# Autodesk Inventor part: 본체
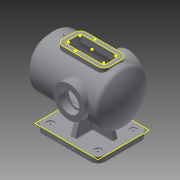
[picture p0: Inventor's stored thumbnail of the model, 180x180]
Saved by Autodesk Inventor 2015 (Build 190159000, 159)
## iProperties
Created: 2021-11
Part Number: 본체
Material: 일반
Document SubType Name: Modeling
Designer: 1016549
Density: 1 g/cm^3
Appearance: 기본값
Author: 1016549
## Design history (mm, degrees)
sketch "스케치1"
  geometry: C1 r 65 at (0, 0); 1 further point
  constraints: 1 centre point, 1 coincident
  dimensions: "d0" = 130 diameter of C1
extrude "돌출1" new body sketch "스케치1" stored distance "d1" = 200; taper "d2" = 0 deg
sketch "스케치2"
  geometry: L1 (100, 65)-(100, -65) reference; L2 (100, -65)-(-100, -65) reference; L3 (-100, -65)-(-100, 65) reference; L4 (-100, 65)-(100, 65) reference; L5 (100, 0)-(-100, 0); A1 r 100 centre (0, 0) between (-75.993, 65) and (-100, 0); 1 further point
  constraints: 3 midpoint, 2 end point, 2 point on circle, 1 centre point, 1 horizontal, 1 point on line
  dimensions: "d3" = 100 radius of A1
revolve "회전1" sketch "스케치2" stored, may be unused: angle "d4" = 90 deg
fillet "모깎기1" dims "d5" = 10
feature "쉘1" dims "d6" = 10
sketch "스케치3"
  geometry: C1 r 55 at (0, 0) reference; C2 r 65 at (0, 0) reference; C3 r 65 at (0, 0)
  constraints: 1 centre point, 1 coincident, 1 concentric
extrude "돌출2" join sketch "스케치3" distance "d7" = 15; taper "d8" = 0 deg
sketch "스케치4"
  geometry: C1 r 65 at (0, 0) reference; C2 r 47.5 at (0, 0)
  constraints: 1 centre point, 1 coincident
  dimensions: "d9" = 95 diameter of C2
extrude "돌출3" join sketch "스케치4" distance "d10" = 10; taper "d11" = 0 deg
sketch "스케치5"
  geometry: C1 r 47.5 at (0, 0) reference
hole "구멍1" sketch "스케치5" at (0, 0) diameter "d12" = 65; stored, may be unused: countersink angle "d16" = 90 deg, drill point angle "d18" = 118 deg; dims "d13" = 6, "d14" = 4, "d15" = 2, "d17" = 30
fillet "모깎기2" dims "d19" = 10
sketch "스케치6"
  geometry: 1 further point
node "작업 평면2"
sketch "스케치7"
  geometry: L1 (-80, -65)-(80, -65); L2 (80, -65)-(80, 65); L3 (80, 65)-(-80, 65); L4 (-80, 65)-(-80, -65); 3 further points
  constraints: 8 end point, 2 midpoint, 2 parallel, 1 horizontal, 1 horizontal alignment, 1 perpendicular, 1 vertical alignment
  dimensions: "d22" = 130 distance of L1.end L2.end; "d23" = 160 distance of L2.end L3.end
extrude "돌출4" join sketch "스케치7" distance "d24" = 14; taper "d25" = 0 deg
sketch "스케치8"
  geometry: L1 (60, -7)-(-60, -7); L2 (-60, -7)-(-60, 7); L3 (-60, 7)-(60, 7); L4 (60, 7)-(60, -7); L5 (60, -7)-(-60, 7); L6 (-60, -7)-(60, 7); L7 (7, -50)-(-7, -50); L8 (-7, -50)-(-7, 50); L9 (-7, 50)-(7, 50); L10 (7, 50)-(7, -50); L11 (7, -50)-(-7, 50); L12 (-7, -50)-(7, 50); 1 further point
  constraints: 24 end point, 4 midpoint, 4 parallel, 2 horizontal, 2 perpendicular
  dimensions: "d28" = 120 distance of L1.start L1.end; "d29" = 14 distance of L3.end L1.start; "d30" = 14 distance of L8.end L9.end; "d31" = 100 distance of L9.end L7.start
extrude "돌출5" join sketch "스케치8" stored distance "d26" = 14; taper "d27" = 0 deg
sketch "스케치9"
  geometry: L1 (60, -7)-(7, -7) reference; L2 (7, -7)-(7, -50) reference; L3 (7, -50)-(-7, -50) reference; L4 (-7, -50)-(-7, -7) reference; L5 (-7, -7)-(-60, -7) reference; L6 (-60, -7)-(-60, 7) reference; L7 (-60, 7)-(-7, 7) reference; L8 (-7, 7)-(-7, 50) reference; L9 (-7, 50)-(7, 50) reference; L10 (7, 50)-(7, 7) reference; L11 (7, 7)-(60, 7) reference; L12 (60, 7)-(60, -7) reference; L13 (-80, -65)-(80, -65) reference; L14 (80, -65)-(80, 65) reference; L15 (80, 65)-(-80, 65) reference; L16 (-80, 65)-(-80, -65) reference; 1 further point
feature "면 기울기1" dims angle "d32" = 20 deg
feature "면 기울기2" dims angle "d33" = 20 deg
feature "면 기울기3" dims angle "d34" = 20 deg
feature "면 기울기4" dims angle "d35" = 20 deg
node "작업 평면3"
sketch "스케치10"
  geometry: L1 (110, -47.5)-(110, 47.5) reference; C1 r 40 at (-17, 0); 2 further points
  constraints: 1 centre point, 1 coincident, 1 horizontal alignment, 1 midpoint
  dimensions: "d112" = 127 distance from line of point (-17, 0) L1
extrude "돌출6" join sketch "스케치10" stored distance "d38" = 14; taper "d39" = 0 deg
node "작업 평면4"
sketch "스케치11"
  geometry: L1 (-60, 30)-(60, 30); L2 (60, 30)-(60, -30); L3 (60, -30)-(-60, -30); L4 (-60, -30)-(-60, 30); L5 (-110, 47.5)-(-110, -47.5) reference; 2 further points
  constraints: 8 end point, 2 parallel, 1 horizontal, 1 horizontal alignment, 1 midpoint, 1 perpendicular
  dimensions: "d41" = 60 distance of L1.end L2.end; "d42" = 120 distance of L2.end L3.end; "d113" = 50 distance between parallel lines of L4 L5
extrude "돌출7" join sketch "스케치11" stored distance "d44" = 14; taper "d45" = 0 deg
fillet "모깎기3" dims "d46" = 15
sketch "스케치12"
  geometry: L1 (-45, 30)-(45, 30) reference; L2 (-60, -15)-(-60, 15) reference; L3 (45, -30)-(-45, -30) reference; L4 (60, 15)-(60, -15) reference; L5 (50, 15)-(50, -15); L6 (45, -20)-(-45, -20); L7 (-50, -15)-(-50, 15); L8 (-45, 20)-(45, 20); A1 r 15 centre (45, 15) between (60, 15) and (45, 30) reference; A2 r 15 centre (-45, 15) between (-45, 30) and (-60, 15) reference; A3 r 15 centre (-45, -15) between (-60, -15) and (-45, -30) reference; A4 r 15 centre (45, -15) between (45, -30) and (60, -15) reference; A5 r 5 centre (45, 15) between (50, 15) and (45, 20); A6 r 5 centre (45, -15) between (45, -20) and (50, -15); A7 r 5 centre (-45, -15) between (-50, -15) and (-45, -20); A8 r 5 centre (-45, 15) between (-45, 20) and (-50, 15); 1 further point
  constraints: 8 end point, 8 point on circle, 4 centre point, 7 other
  dimensions: "d47" = 10 distance between parallel lines of L1 L8
extrude "돌출8" cut sketch "스케치12" distance "d48" = 20; taper "d49" = 0 deg
sketch "스케치13"
  geometry: 1 further point
sketch "스케치14"
  geometry: L1 (-127, 47.5)-(-127, -47.5) reference; C1 r 40 at (0, 0)
  constraints: 1 centre point
  dimensions: "d111" = 127 distance from line of C1.centre L1
hole "구멍2" sketch "스케치14" at (0, 0) diameter "d50" = 42; stored, may be unused: countersink angle "d54" = 90 deg, drill point angle "d56" = 118 deg; dims "d51" = 6, "d52" = 52, "d53" = 18, "d55" = 30
sketch "스케치16"
  geometry: C1 r 26 at (0, 0) reference; 1 further point
  constraints: 1 vertical alignment
  dimensions: "d57" = 32.5 distance of C1.centre point (0, 32.5)
hole "구멍3" sketch "스케치16" at (0, 32.5) diameter "d58" = 3.242; stored, may be unused: countersink angle "d62" = 90 deg, drill point angle "d64" = 118 deg; dims "d59" = 11, "d60" = 52, "d61" = 18, "d63" = 13
sketch "스케치17"
  geometry: C1 r 32.5 at (0, 0) reference; 1 further point
  constraints: 1 horizontal alignment
  dimensions: "d68" = 40 distance of C1.centre point (40, 0)
hole "구멍4" sketch "스케치17" at (40, 0) diameter "d69" = 3.242; stored, may be unused: countersink angle "d73" = 90 deg, drill point angle "d75" = 118 deg; dims "d70" = 11, "d71" = 52, "d72" = 18, "d74" = 13
sketch "스케치18"
  geometry: 2 further points
  dimensions: "d79" = 17 horizontal distance of point (-17, 25) point (0, 0); "d80" = 25 vertical distance of point (-17, 25) point (0, 0)
hole "구멍5" sketch "스케치18" at (-17, 25) diameter "d81" = 3.242; stored, may be unused: countersink angle "d85" = 90 deg, drill point angle "d87" = 118 deg; dims "d82" = 9, "d83" = 52, "d84" = 18, "d86" = 11
sketch "스케치19"
  geometry: C1 r 1.621 at (-17, 25) reference; 3 further points
  constraints: 2 horizontal alignment
  dimensions: "d88" = 55 horizontal distance of point (-72, 0) C1.centre; "d89" = 55 horizontal distance of point (38, 0) C1.centre
hole "구멍6" sketch "스케치19" at (-72, 0), (38, 0) diameter "d90" = 3.242; stored, may be unused: countersink angle "d94" = 90 deg, drill point angle "d96" = 118 deg; dims "d91" = 9, "d92" = 52, "d93" = 18, "d95" = 11
fillet "모깎기4" dims "d97" = 20
sketch "스케치20"
  geometry: A1 r 20 centre (60, 45) between (80, 45) and (60, 65) reference; A2 r 20 centre (-60, 45) between (-60, 65) and (-80, 45) reference; A3 r 20 centre (-60, -45) between (-80, -45) and (-60, -65) reference; A4 r 20 centre (60, -45) between (60, -65) and (80, -45) reference; 1 further point
hole "구멍7" sketch "스케치20" at (-60, -45), (-60, 45), (60, 45), (60, -45) diameter "d98" = 3.242; stored, may be unused: countersink angle "d102" = 90 deg, drill point angle "d104" = 118 deg; dims "d99" = 9, "d100" = 18, "d101" = 2, "d103" = 11
fillet "모깎기5" dims "d105" = 3
fillet "모깎기6" dims "d106" = 3
fillet "모깎기7" dims "d107" = 3
sketch "스케치21"
  geometry: L1 (0, 0)-(120, 0) reference; 3 further points
  constraints: 1 midpoint, 1 vertical alignment, 1 other
  dimensions: "d108" = 5 distance from line of L1 point (60, 5)
feature "엠보싱1" sketch "스케치21" dims "d109" = 0.5, "d110" = 0
sketch "스케치22"
  geometry: L1 (-45, 20)-(45, 20) reference; L2 (50, 15)-(50, -15) reference; L3 (45, -20)-(-45, -20) reference; L4 (-50, -15)-(-50, 15) reference; L5 (-45, 30)-(45, 30) reference; L6 (-60, -15)-(-60, 15) reference; L7 (45, -30)-(-45, -30) reference; L8 (60, 15)-(60, -15) reference; C1 r 1.621 at (-17, -25) reference; C2 r 1.621 at (-17, 25) reference; A1 r 5 centre (45, 15) between (50, 15) and (45, 20) reference; A2 r 5 centre (45, -15) between (45, -20) and (50, -15) reference; A3 r 5 centre (-45, -15) between (-50, -15) and (-45, -20) reference; A4 r 5 centre (-45, 15) between (-45, 20) and (-50, 15) reference; A5 r 15 centre (45, 15) between (60, 15) and (45, 30) reference; A6 r 15 centre (-45, 15) between (-45, 30) and (-60, 15) reference; A7 r 15 centre (-45, -15) between (-60, -15) and (-45, -30) reference; A8 r 15 centre (45, -15) between (45, -30) and (60, -15) reference; 1 further point
node "솔리드1"
mirror "대칭1"
mirror "대칭2"
pattern_circular "원형 패턴1" dims angle "d66" = 360 deg
mirror "대칭3"
pattern_circular "원형 패턴2" dims angle "d77" = 360 deg
mirror "대칭4"
node "절단 모서리 투영1"
other parameters: "d21" = -114, "d36" = -75
